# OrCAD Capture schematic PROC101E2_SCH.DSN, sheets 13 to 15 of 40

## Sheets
13 33. IO EXPANDER & TEST HEADER: size C; title: IO EXPANDER
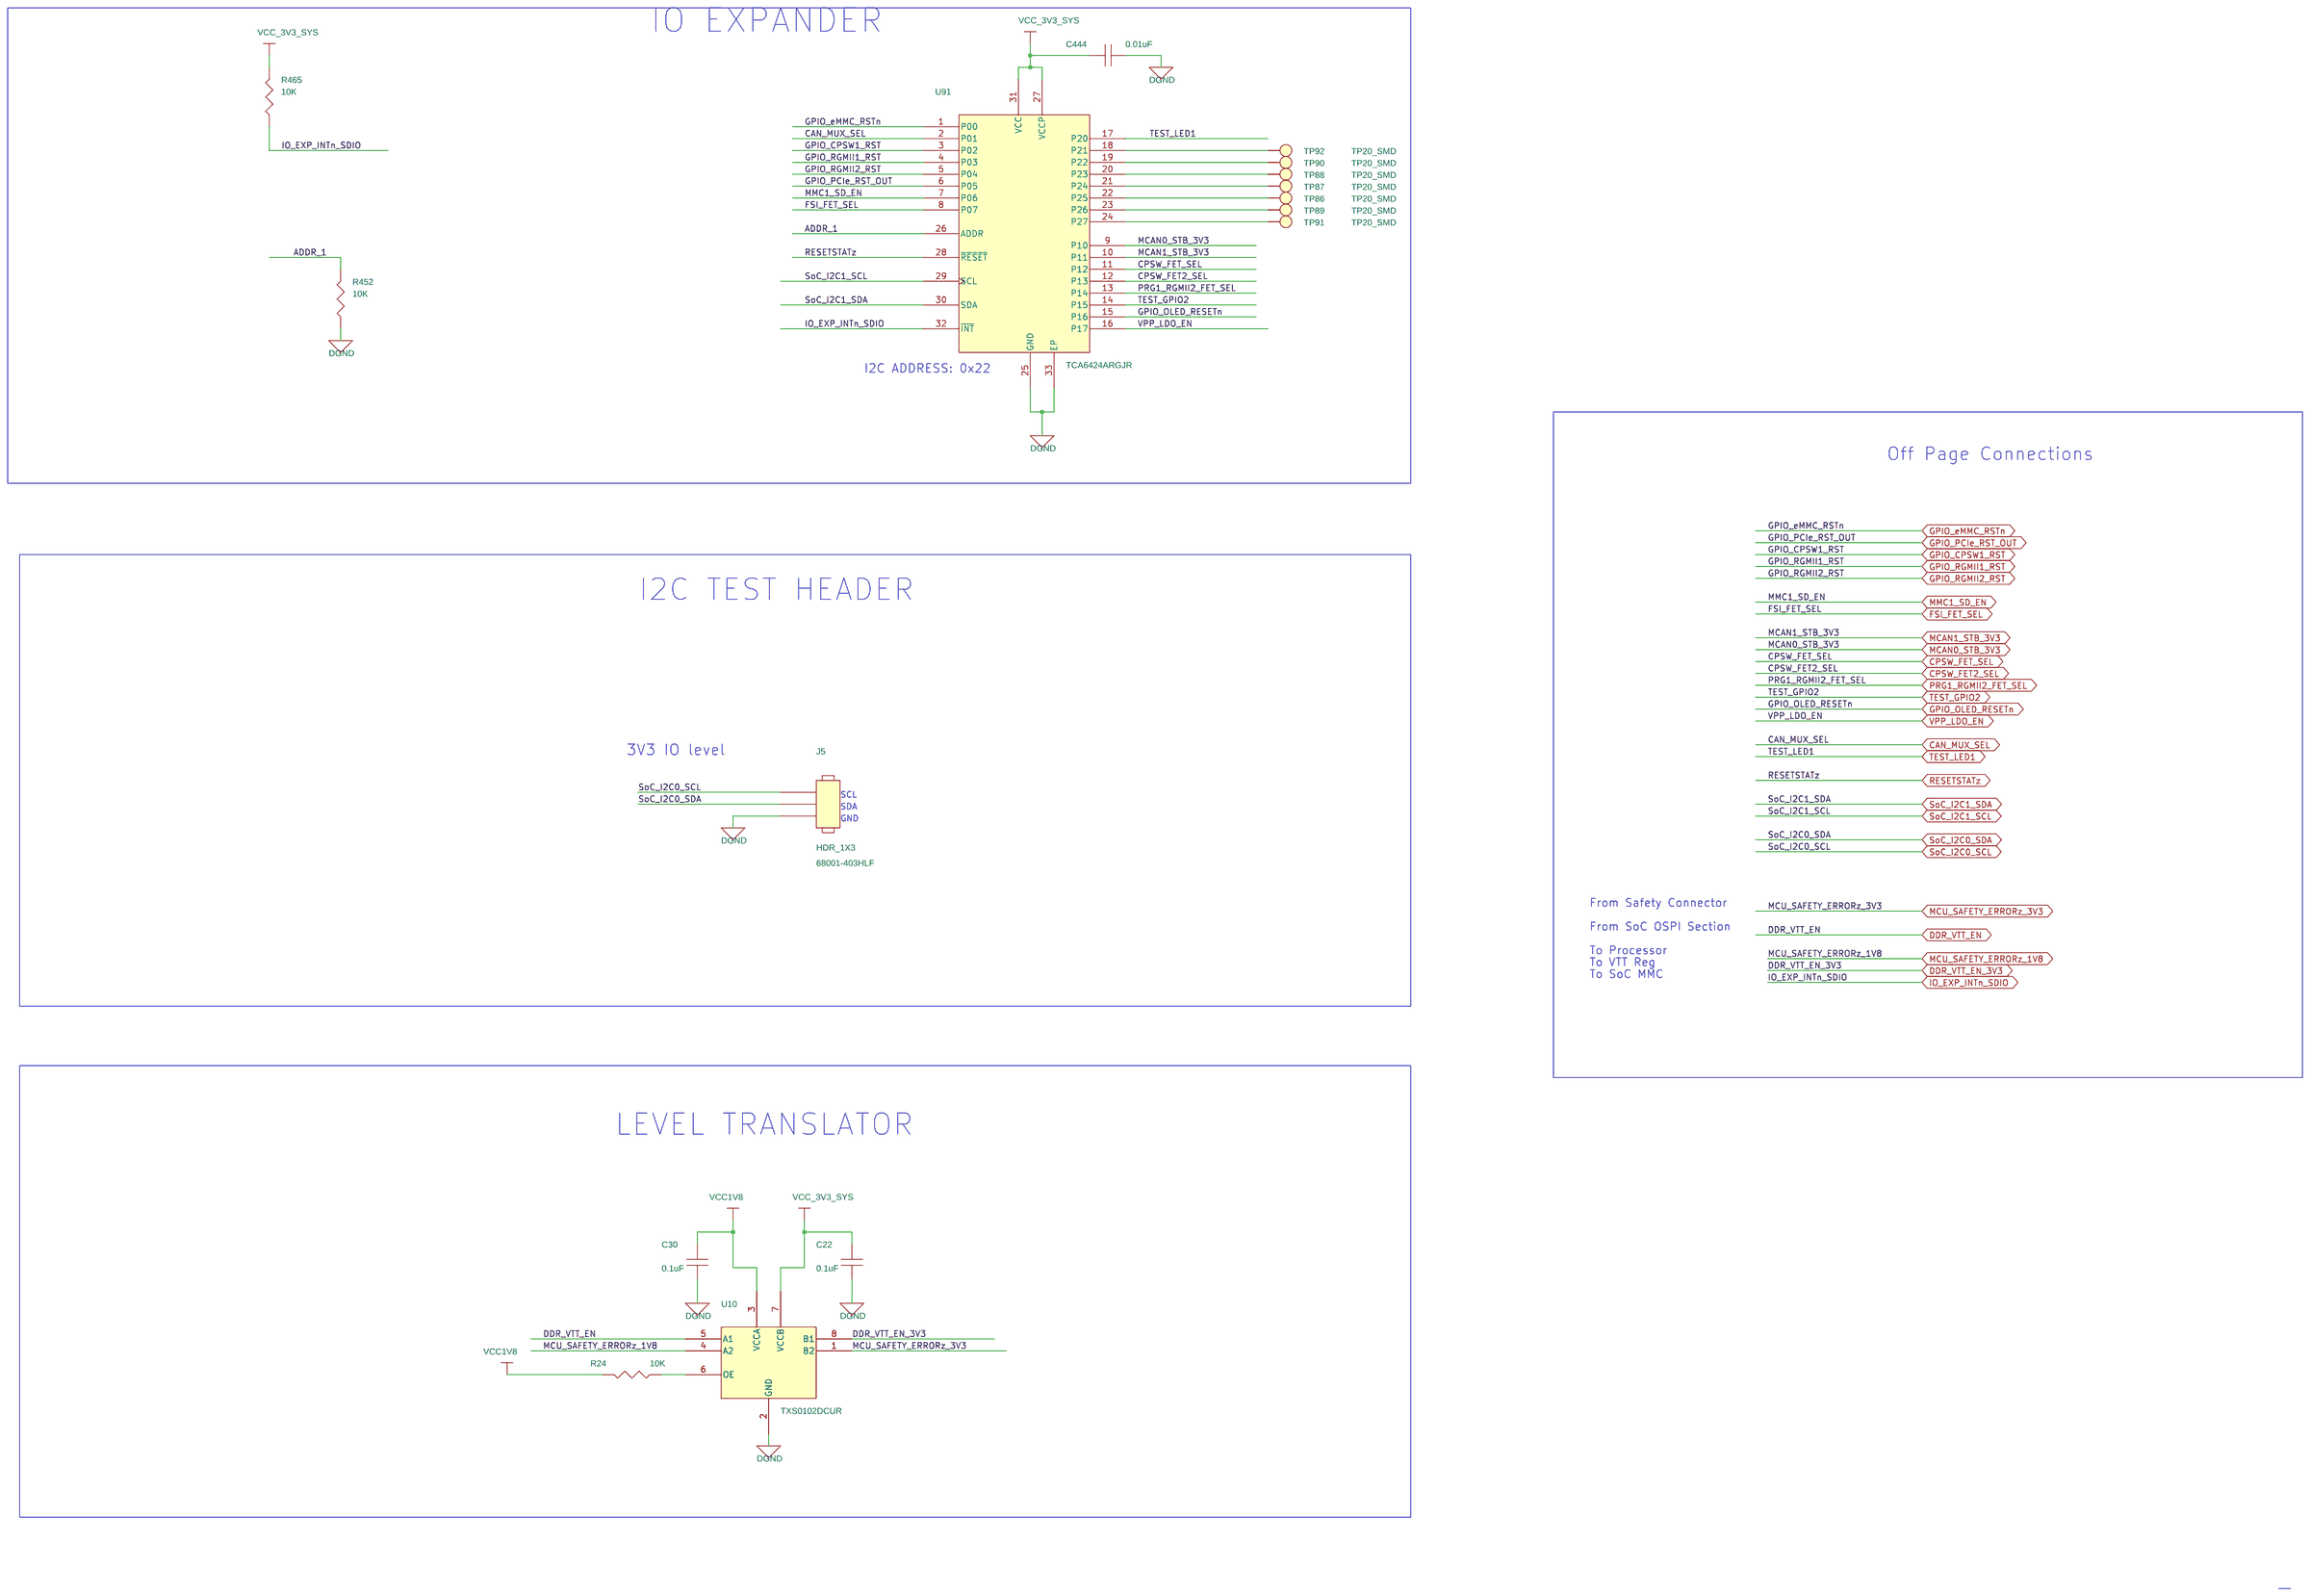
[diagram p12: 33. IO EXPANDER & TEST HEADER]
14 21. CURRENT MONITORING DEVICES: size C; title: CURRENT MONITORING DEVICES
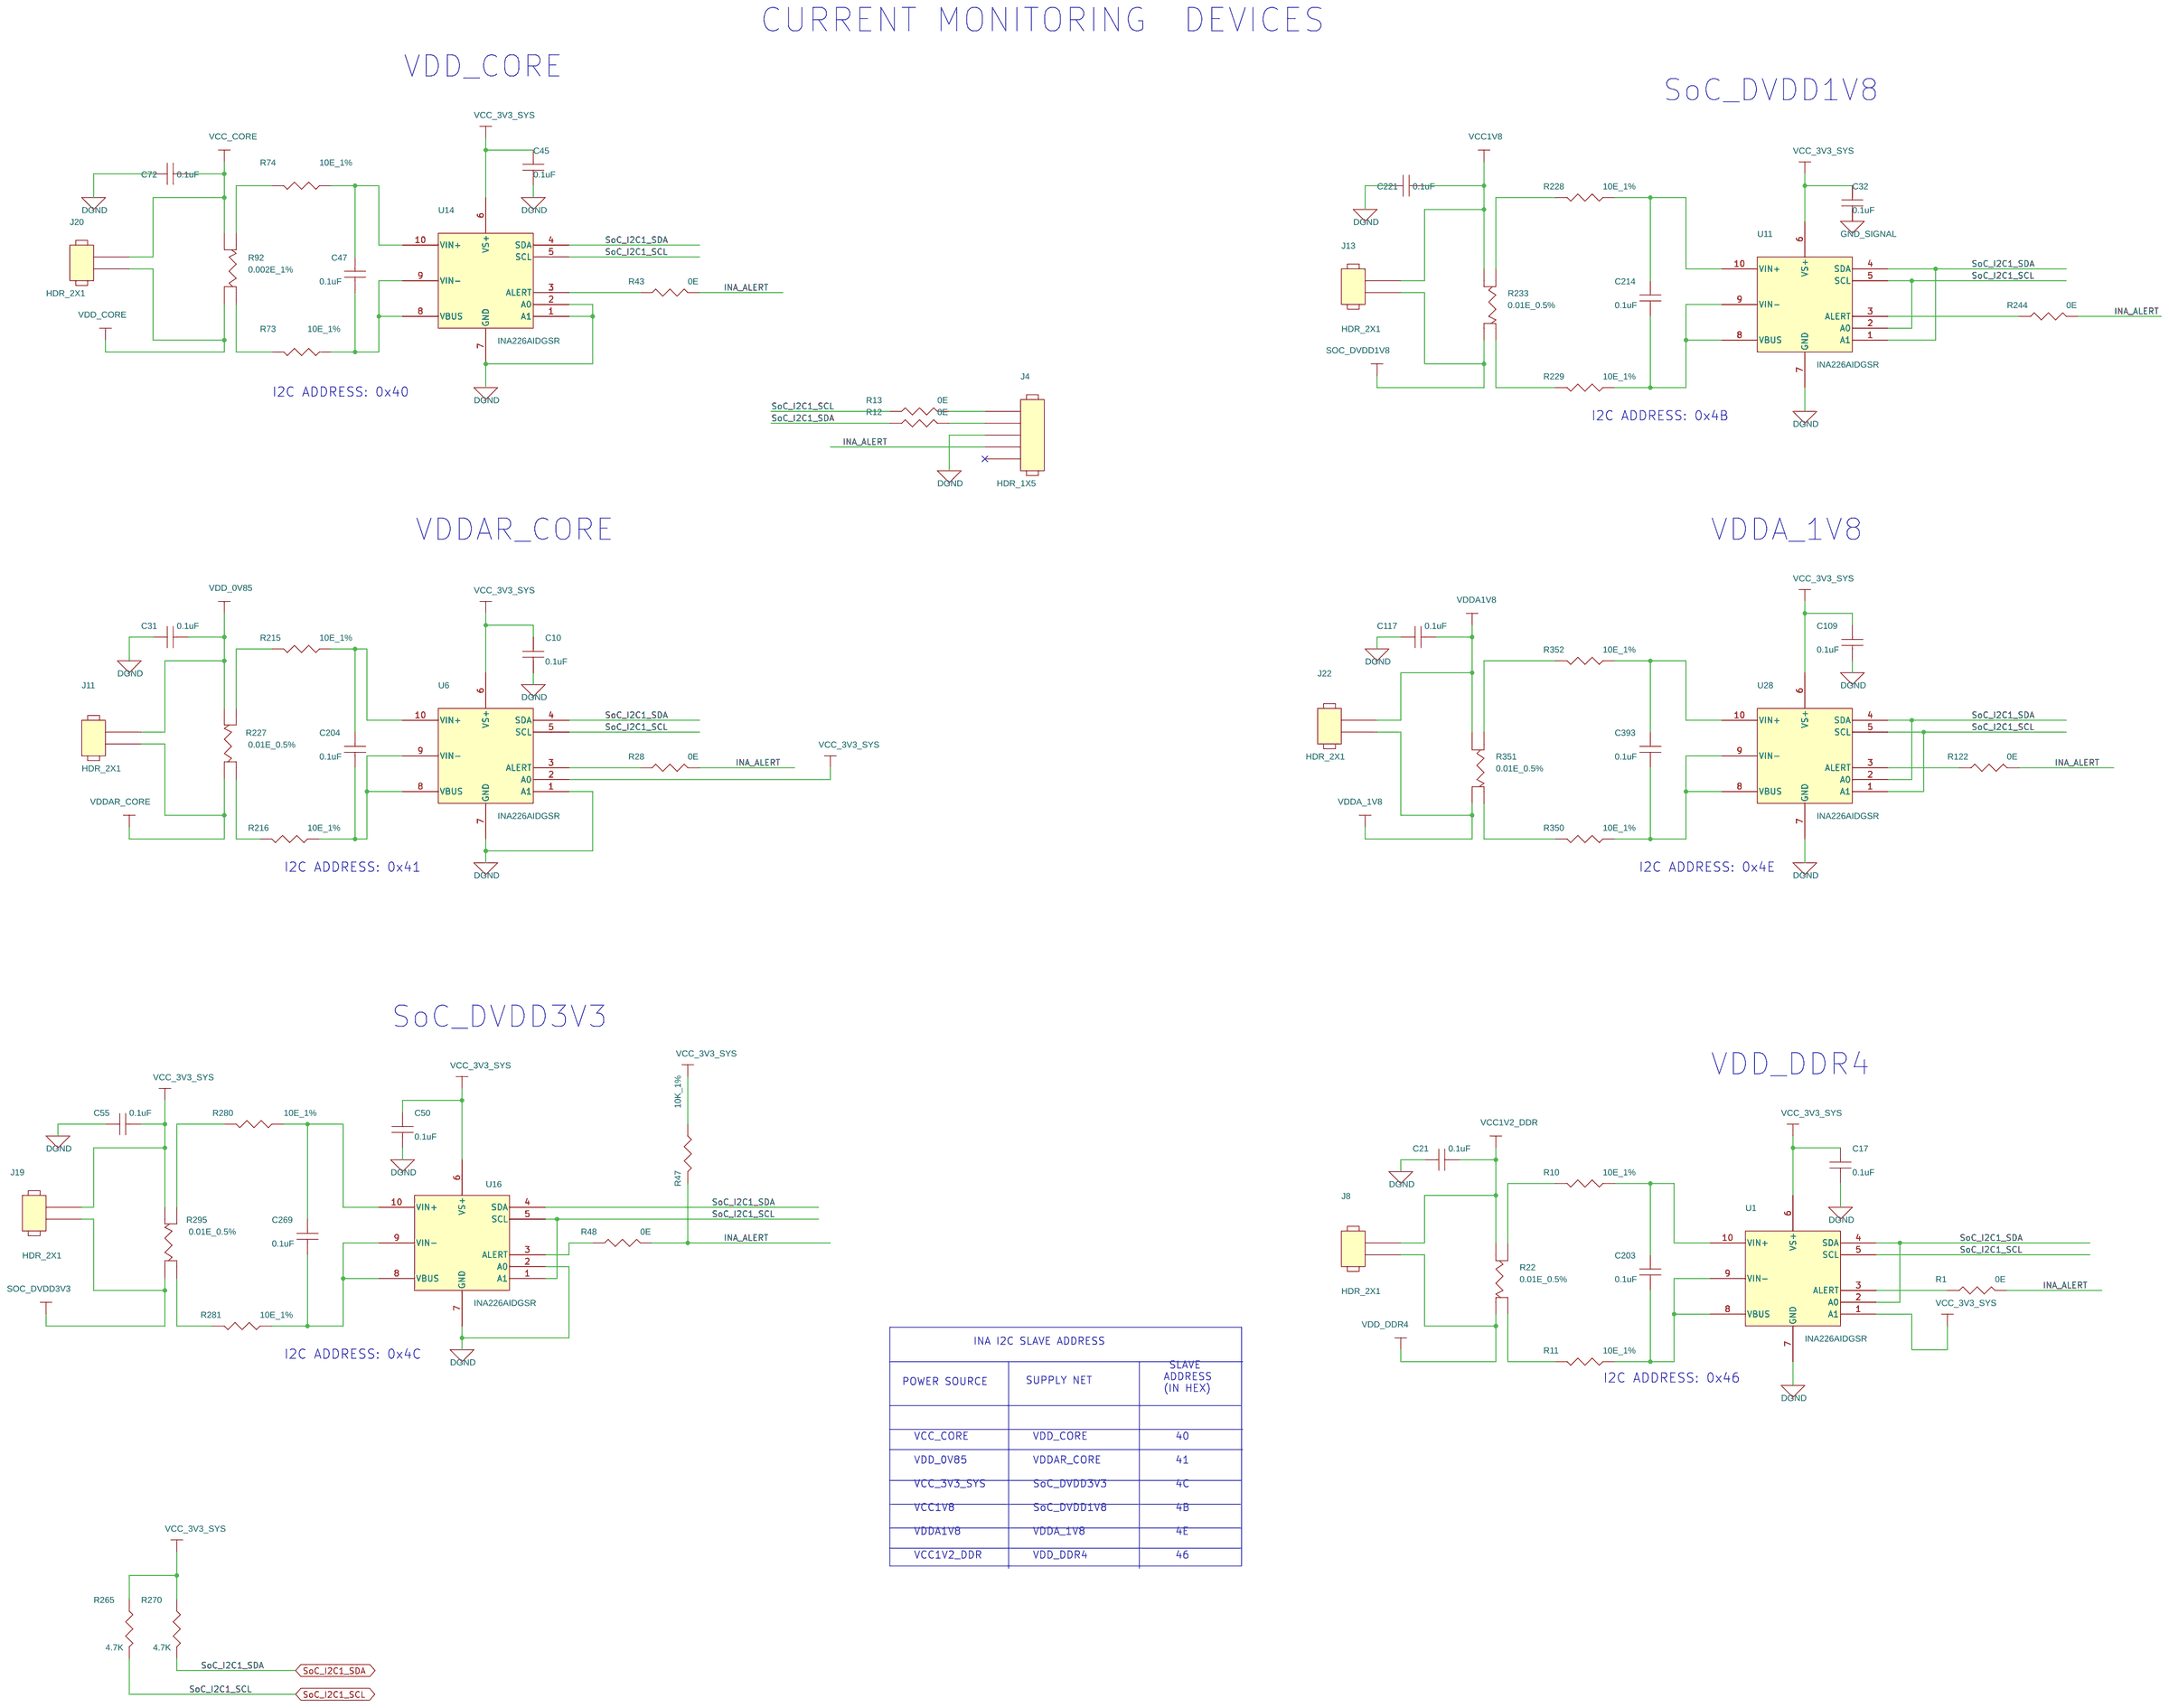
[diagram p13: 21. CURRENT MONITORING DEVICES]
15 38. SoC POWER SUPPLY: size C; title: SoC POWER SUPPLY
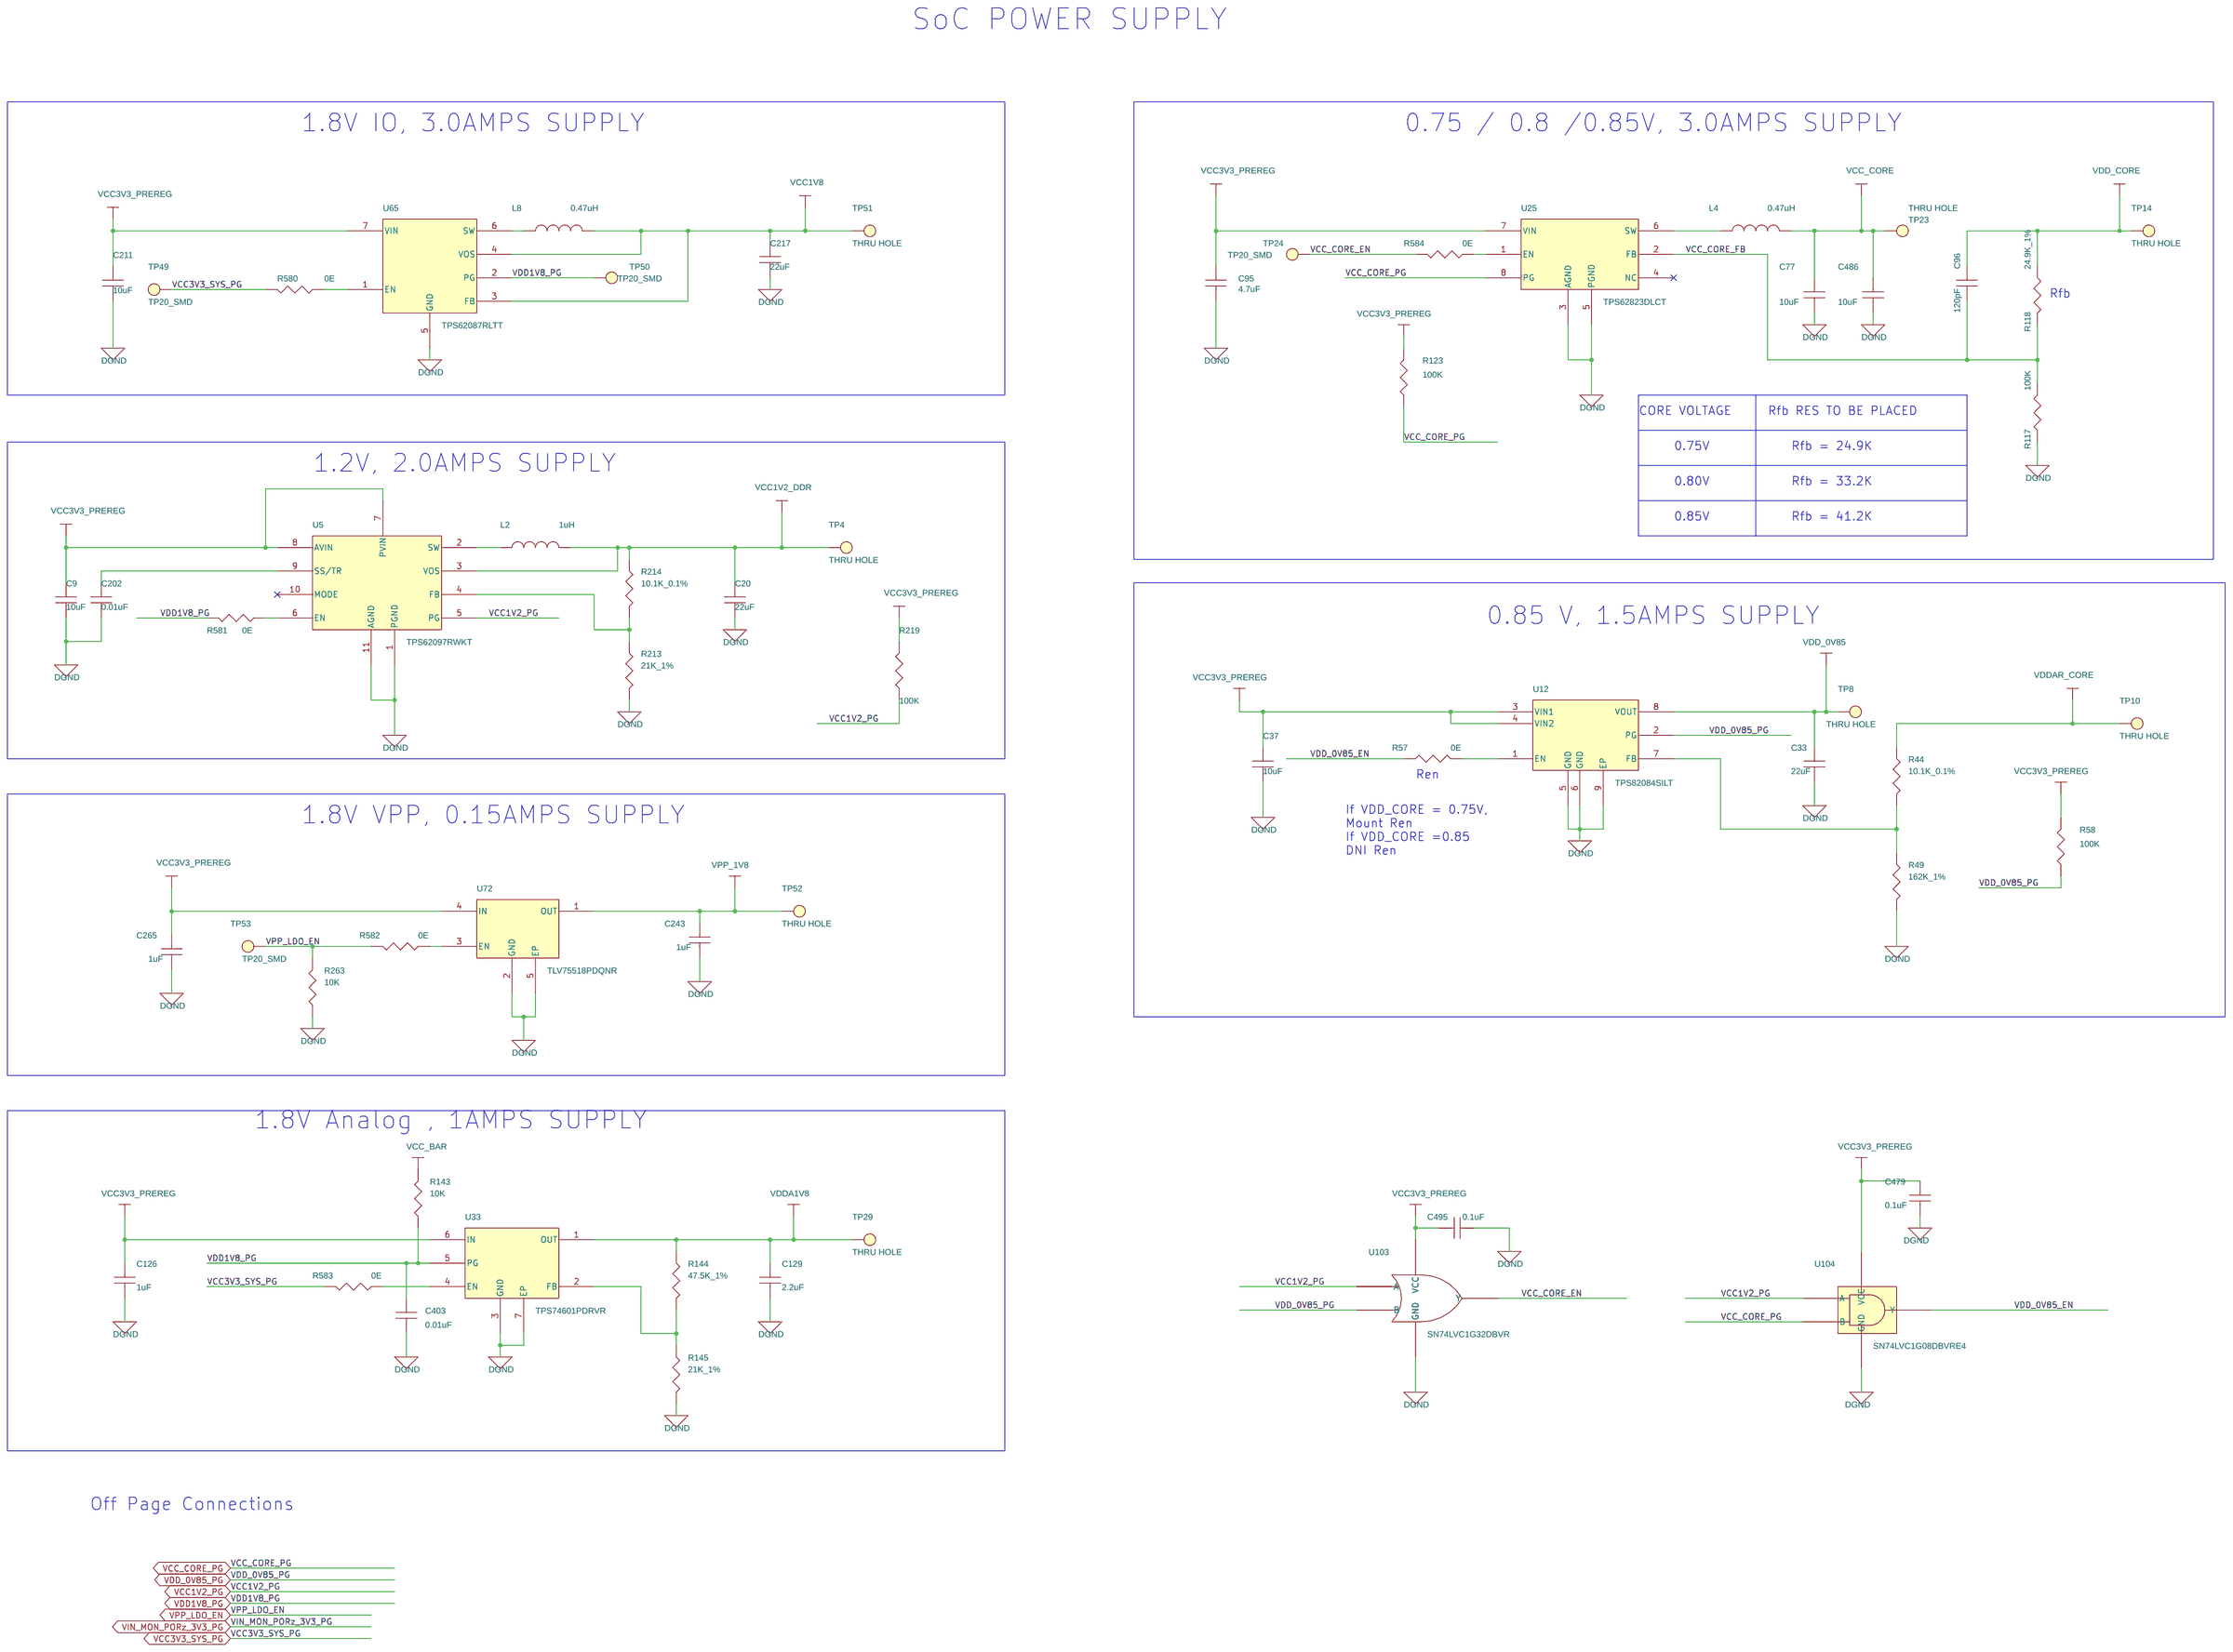
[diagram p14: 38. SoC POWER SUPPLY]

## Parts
sheet 21. CURRENT MONITORING DEVICES
C10  0.1uF  [CAP0402_0-75]
C17  0.1uF  [CAP0402_0-75]
C21  0.1uF  [CAP0402_0-75]
C31  0.1uF  [CAP0402_0-75]
C32  0.1uF  [CAP0402_0-75]
C45  0.1uF  [CAP0402_0-75]
C47  0.1uF  [CAP0402_0-75]
C50  0.1uF  [CAP0402_0-75]
C55  0.1uF  [CAP0402_0-75]
C72  0.1uF  [CAP0402_0-75]
C109  0.1uF  [CAP0402_0-75]
C117  0.1uF  [CAP0402_0-75]
C203  0.1uF  [CAP0402_0-75]
C204  0.1uF  [CAP0402_0-75]
C214  0.1uF  [CAP0402_0-75]
C221  0.1uF  [CAP0402_0-75]
C269  0.1uF  [CAP0402_0-75]
C393  0.1uF  [CAP0402_0-75]
J4  HDR_1X5  [HDR_5X1_100_S_T_11-2]
J8  HDR_2X1  [HDR_2X1_100_S_T_10-8]
J11  HDR_2X1  [HDR_2X1_100_S_T_10-8]
J13  HDR_2X1  [HDR_2X1_100_S_T_10-8]
J19  HDR_2X1  [HDR_2X1_100_S_T_10-8]
J20  HDR_2X1  [HDR_2X1_100_S_T_10-8]
J22  HDR_2X1  [HDR_2X1_100_S_T_10-8]
R1  0E  [RES0402_0-5]
R10  10E_1%  [RES0402_0-5]
R11  10E_1%  [RES0402_0-5]
R12  0E  [RES0402_0-5]
R13  0E  [RES0402_0-5]
R22  0.01E_0.5%  [RES1206-4TERM_0-75]
R28  0E  [RES0402_0-5]
R43  0E  [RES0402_0-5]
R47  10K_1%  [RES0402_0-5]
R48  0E  [RES0402_0-5]
R73  10E_1%  [RES0402_0-5]
R74  10E_1%  [RES0402_0-5]
R92  0.002E_1%  [RES2512-4TERM_0-75]
R122  0E  [RES0402_0-5]
R215  10E_1%  [RES0402_0-5]
R216  10E_1%  [RES0402_0-5]
R227  0.01E_0.5%  [RES1206-4TERM_0-75]
R228  10E_1%  [RES0402_0-5]
R229  10E_1%  [RES0402_0-5]
R233  0.01E_0.5%  [RES1206-4TERM_0-75]
R244  0E  [RES0402_0-5]
R265  4.7K  [RES0402_0-5]
R270  4.7K  [RES0402_0-5]
R280  10E_1%  [RES0402_0-5]
R281  10E_1%  [RES0402_0-5]
R295  0.01E_0.5%  [RES1206-4TERM_0-75]
R350  10E_1%  [RES0402_0-5]
R351  0.01E_0.5%  [RES1206-4TERM_0-75]
R352  10E_1%  [RES0402_0-5]
U1  INA226AIDGSR  [MSOP10_19-68_120X120_1-1]
U6  INA226AIDGSR  [MSOP10_19-68_120X120_1-1]
U11  INA226AIDGSR  [MSOP10_19-68_120X120_1-1]
U14  INA226AIDGSR  [MSOP10_19-68_120X120_1-1]
U16  INA226AIDGSR  [MSOP10_19-68_120X120_1-1]
U28  INA226AIDGSR  [MSOP10_19-68_120X120_1-1]
sheet 33. IO EXPANDER & TEST HEADER
C22  0.1uF  [CAP0402_0-75]
C30  0.1uF  [CAP0402_0-75]
C444  0.01uF  [CAP0402_0-75]
J5  HDR_1X3  [HDR_3X1_100_S_T]
R24  10K  [RES0402_0-5]
R452  10K  [RES0402_0-5]
R465  10K  [RES0402_0-5]
TP86  TP20_SMD  [TP20_SMD]
TP87  TP20_SMD  [TP20_SMD]
TP88  TP20_SMD  [TP20_SMD]
TP89  TP20_SMD  [TP20_SMD]
TP90  TP20_SMD  [TP20_SMD]
TP91  TP20_SMD  [TP20_SMD]
TP92  TP20_SMD  [TP20_SMD]
U10  TXS0102DCUR  [VSSOP8_19-68_85X95_0-9]
U91  TCA6424ARGJR  [QFN32_19-68_200X200]
sheet 38. SoC POWER SUPPLY
C9  10uF  [CAP0402_0-75]
C20  22uF  [CAP0603_1]
C33  22uF  [CAP0603_1]
C37  10uF  [CAP0402_0-75]
C77  10uF  [CAP0402_0-75]
C95  4.7uF  [CAP0603_1]
C96  120pF  [CAP0402_0-75]
C126  1uF  [CAP0402_0-75]
C129  2.2uF  [CAP0402_0-75]
C202  0.01uF  [CAP0402_0-75]
C211  10uF  [CAP0603_1]
C217  22uF  [CAP0603_1]
C243  1uF  [CAP0402_0-75]
C265  1uF  [CAP0402_0-75]
C403  0.01uF  [CAP0402_0-75]
C479  0.1uF  [CAP0402_0-75]
C486  10uF  [CAP0402_0-75]
C495  0.1uF  [CAP0402_0-75]
L2  1uH  [IND_744316100_230X220_SMD_4-3]
L4  0.47uH  [IND_744373460047_270X270_SMD_3]
L8  0.47uH  [IND_744373460047_270X270_SMD_3]
R44  10.1K_0.1%  [RES0603_0-75]
R49  162K_1%  [RES0402_0-5]
R57  0E  [RES0402_0-5]
R58  100K  [RES0402_0-5]
R117  100K  [RES0402_0-5]
R118  24.9K_1%  [RES0402_0-5]
R123  100K  [RES0402_0-5]
R143  10K  [RES0402_0-5]
R144  47.5K_1%  [RES0402_0-5]
R145  21K_1%  [RES0402_0-5]
R213  21K_1%  [RES0402_0-5]
R214  10.1K_0.1%  [RES0603_0-75]
R219  100K  [RES0402_0-5]
R263  10K  [RES0402_0-5]
R580  0E  [RES0402_0-5]
R581  0E  [RES0402_0-5]
R582  0E  [RES0402_0-5]
R583  0E  [RES0402_0-5]
R584  0E  [RES0402_0-5]
TP4  THRU HOLE  [TP_40X65]
TP8  THRU HOLE  [TP_40X65]
TP10  THRU HOLE  [TP_40X65]
TP14  THRU HOLE  [TP_40X65]
TP23  THRU HOLE  [TP_40X65]
TP24  TP20_SMD  [TP20_SMD]
TP29  THRU HOLE  [TP_40X65]
TP49  TP20_SMD  [TP20_SMD]
TP50  TP20_SMD  [TP20_SMD]
TP51  THRU HOLE  [TP_40X65]
TP52  THRU HOLE  [TP_40X65]
TP53  TP20_SMD  [TP20_SMD]
U5  TPS62097RWKT  [VQFNHR11_TPS62097_80X80_1]
U12  TPS82084SILT  [uSIP8_TPS82084_110X120_1-4]
U25  TPS62823DLCT  [VSONHR8_TPS62823_60X80_1]
U33  TPS74601PDRVR  [SON6_25-59_85X85_0-8]
U65  TPS62087RLTT  [VSONHR7_TPS62085_80X80_1]
U72  TLV75518PDQNR  [X2SON4_TLV71318P_40X40_0-4]
U103  SN74LVC1G32DBVR  [SOT23-5_1-5]
U104  SN74LVC1G08DBVRE4  [SOT23-5]

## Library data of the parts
C10 C17 C21 C22 C30-C32 C45 C47 C50 C55 C72 C109 C117 C203 C204 C214 C221 C269 C393 C479 C495 = CAP: CAP CERAMIC 0.1uF 25V 20% X5R 0402; Alt_Mfr_name: YAGEO AMERICA; Alt_Mfr_part_number: CC0402KRX5R8BB104; Chkd/date: MANIRAJA/170820; Crtd /date: ALVY/170820; Custom_Duty: 15%; Customs_HS_Code: 85322990; Distributor_name: DIGIKEY; Distributor_part_number: 732-7495-1-ND; Footprint Path: Y:\MIS_DATABASE\Library\ALTIUM_TOOL\PCB_FOOTPRINTS\Altium_Footprint_Lib.PcbLib; Height: 0.55MM; Library Path: Y:\MIS_DATABASE\Library\ALTIUM_TOOL\SCHEMATICS_PARTS\MS_DISCRETE_Library.schlib; Mfr_name: WURTH ELECTRONICS; Mfr_part_number: 885012105018; Mistral Part No: 120020080003-R; Package: 0402; Part_type: CAPACITORS\CERAMIC; Project: AM64x_EVM_BRD; RoHS: RoHS; Temperature: -55°C+85°C; Tolerance: 20%; Voltage: 25V; Wattage: NA; Weight: 0.65mg; Datasheet: Y:\MIS_DATABASE\DATASHEETS\CAPACITORS\885012105018.PDF
J4 = HEADER_5X1: CON HDR 1X5 2.54MM PITCH ST TH; Chkd/date: VASANTHA/310117; Crtd /date: MAZHAR/280405; Custom_Duty: 24%; Customs_HS_Code: 85369090; Distributor_name: DIGIKEY; Distributor_part_number: WM4003-ND; Footprint Path: Y:\MIS_DATABASE\Library\ALTIUM_TOOL\PCB_FOOTPRINTS\Altium_Footprint_Lib.PcbLib; Height: 11.17MM; Library Path: Y:\MIS_DATABASE\Library\ALTIUM_TOOL\SCHEMATICS_PARTS\MS_CONNECTOR_Library.schlib; Mfr_name: MOLEX; Mfr_part_number: 22-03-2051; Mistral Part No: 150009030262-R; Package: THRU-HOLE; Part_type: CONNECTOR\HEADERS; Project: HSWD; RoHS: RoHS; Temperature: NA; Tolerance: NA; Voltage: NA; Wattage: NA; Weight: 343mg; Datasheet: Y:\MIS_DATABASE\DATASHEETS\CONNECTORS\MOLEX022032021.PDF
J8 J11 J13 J19 J20 J22 = HEADER_2X1: CON HDR 2X1 2.54MM PITCH ST TH; Chkd/date: VASANTHA/060117; Crtd /date: MAZHAR/280405; Custom_Duty: 24%; Customs_HS_Code: 85369090; Distributor_name: DIGIKEY; Distributor_part_number: WM4000-ND; Footprint Path: Y:\MIS_DATABASE\Library\ALTIUM_TOOL\PCB_FOOTPRINTS\Altium_Footprint_Lib.PcbLib; Height: 10.79MM; Library Path: Y:\MIS_DATABASE\Library\ALTIUM_TOOL\SCHEMATICS_PARTS\MS_Connector_Library.schlib; Mfr_name: MOLEX; Mfr_part_number: 22-03-2021; Mistral Part No: 150009030246-R; Package: THRU-HOLE; Part_type: CONNECTOR\HEADERS; Project: FPGA EXTENDER CARD; RoHS: RoHS; Temperature: -0°C+75°C; Tolerance: NA; Voltage: NA; Wattage: NA; Weight: 139gm; Datasheet: Y:\MIS_DATABASE\DATASHEETS\CONNECTORS\HEADER_X4030.PDF
R1 R28 R43 R48 R122 R244 = RESISTOR: RES 0E 1/16W JUMPER 0402; Assembly: DNI; Chkd/date: VASANTHA/201216; Crtd /date: MUDDU/190810; Custom_Duty: 15%; Customs_HS_Code: 85332119; Distributor_name: DIGIKEY; Distributor_part_number: 541-0.0JCT-ND; Footprint Path: Y:\MIS_DATABASE\Library\ALTIUM_TOOL\PCB_FOOTPRINTS\Altium_Footprint_Lib.PcbLib; Height: 0.40MM; Library Path: Y:\MIS_DATABASE\Library\ALTIUM_TOOL\SCHEMATICS_PARTS\MS_DISCRETE_Library.schlib; Mfr_name: VISHAY; Mfr_part_number: CRCW04020000Z0ED; Mistral Part No: 110010080019-R; Package: 0402; Part_type: RESISTORS\FIXED; Project: PB_BUGBASE; RoHS: RoHS; Temperature: -55°C+155°C; Tolerance: NA; Voltage: NA; Wattage: 1/16W; Weight: 0.65mg; Datasheet: Y:\MIS_DATABASE\DATASHEETS\RESISTORS\CRCW0603.PDF
R10 R11 R73 R74 R215 R216 R228 R229 R280 R281 R350 R352 = RESISTOR: RES 10E 1/16W 1% 0402; Chkd/date: MANIRAJA/070218; Crtd /date: ALVY/070218; Custom_Duty: 15%; Customs_HS_Code: 85332119; Distributor_name: DIGIKEY; Distributor_part_number: 311-10.0LRCT-ND; Footprint Path: Y:\MIS_DATABASE\Library\ALTIUM_TOOL\PCB_FOOTPRINTS\Altium_Footprint_Lib.PcbLib; Height: 0.40MM; Library Path: Y:\MIS_DATABASE\Library\ALTIUM_TOOL\SCHEMATICS_PARTS\MS_DISCRETE_Library.schlib; Mfr_name: YAGEO AMERICA; Mfr_part_number: RC0402FR-0710RL; Mistral Part No: 110018020004-R; Package: 0402; Part_type: RESISTORS\FIXED; Project: TI_MAXIE_CPB; RoHS: RoHS; Temperature: -55°C+155°C; Tolerance: 1%; Voltage: NA; Wattage: 1/16W; Weight: 0.65mg; Datasheet: Y:\MIS_DATABASE\DATASHEETS\RESISTORS\RCXXXXL-SER_MAR18.PDF
R12 R13 R57 R580-R584 = RESISTOR: RES 0E 1/16W JUMPER 0402; Chkd/date: VASANTHA/201216; Crtd /date: MUDDU/190810; Custom_Duty: 15%; Customs_HS_Code: 85332119; Distributor_name: DIGIKEY; Distributor_part_number: 541-0.0JCT-ND; Footprint Path: Y:\MIS_DATABASE\Library\ALTIUM_TOOL\PCB_FOOTPRINTS\Altium_Footprint_Lib.PcbLib; Height: 0.40MM; Library Path: Y:\MIS_DATABASE\Library\ALTIUM_TOOL\SCHEMATICS_PARTS\MS_DISCRETE_Library.schlib; Mfr_name: VISHAY; Mfr_part_number: CRCW04020000Z0ED; Mistral Part No: 110010080019-R; Package: 0402; Part_type: RESISTORS\FIXED; Project: PB_BUGBASE; RoHS: RoHS; Temperature: -55°C+155°C; Tolerance: NA; Voltage: NA; Wattage: 1/16W; Weight: 0.65mg; Datasheet: Y:\MIS_DATABASE\DATASHEETS\RESISTORS\CRCW0603.PDF
R22 R227 R233 R295 R351 = RESISTOR-4TERM: RES 0.01E 1/2W 0.5% 1206-4; Chkd/date: MANIRAJA/260917; Crtd /date: MANIRAJA/260917; Custom_Duty: 15%; Customs_HS_Code: 85332119; Distributor_name: DIGIKEY; Distributor_part_number: LVK12R010DERCT-ND; Footprint Path: Y:\MIS_DATABASE\Library\ALTIUM_TOOL\PCB_FOOTPRINTS\Altium_Footprint_Lib.PcbLib; Height: 0.65MM; Library Path: Y:\MIS_DATABASE\Library\ALTIUM_TOOL\SCHEMATICS_PARTS\MS_DISCRETE_Library.schlib; Mfr_name: OHMITE; Mfr_part_number: LVK12R010DER; Mistral Part No: 110017090009-R; Package: 1206-4; Part_type: RESISTORS\FIXED; Project: TI_MAXIE_CPB; RoHS: RoHS; Temperature: -40°C+125°C; Tolerance: 0.5%; Voltage: NA; Wattage: 1/2W; Weight: 16.2mg; Datasheet: Y:\MIS_DATABASE\DATASHEETS\RESISTORS\LVK-SERIES.PDF
R47 = RESISTOR: RES 10K 1/16W 1% 0402; Chkd/date: VASANTHA/201216; Crtd /date: GEETHA/290506; Custom_Duty: 15%; Customs_HS_Code: 85332119; Distributor_name: DIGIKEY; Distributor_part_number: 311-10.0KLRTR-ND; Footprint Path: Y:\MIS_DATABASE\Library\ALTIUM_TOOL\PCB_FOOTPRINTS\Altium_Footprint_Lib.PcbLib; Height: 0.40MM; Library Path: Y:\MIS_DATABASE\Library\ALTIUM_TOOL\SCHEMATICS_PARTS\MS_DISCRETE_Library.schlib; Mfr_name: YAGEO AMERICA; Mfr_part_number: RC0402FR-0710KL; Mistral Part No: 110015090015-R; Package: 0402; Part_type: RESISTORS\FIXED; Project: VOCERA; RoHS: RoHS; Temperature: -55°C+155°C; Tolerance: 1%; Voltage: NA; Wattage: 1/16W; Weight: 0.65mg; Datasheet: Y:\MIS_DATABASE\DATASHEETS\RESISTORS\RCXXXXL-SER_MAR18.PDF
R92 = RESISTOR-4TERM: RES 0.002E 2W 1% 2512-4; Chkd/date: MANIRAJA/260917; Crtd /date: MANIRAJA/260917; Custom_Duty: 15%; Customs_HS_Code: 85332119; Distributor_name: DIGIKEY; Distributor_part_number: LVK25R002FERCT-ND; Footprint Path: Y:\MIS_DATABASE\Library\ALTIUM_TOOL\PCB_FOOTPRINTS\Altium_Footprint_Lib.PcbLib; Height: 0.70MM; Library Path: Y:\MIS_DATABASE\Library\ALTIUM_TOOL\SCHEMATICS_PARTS\MS_DISCRETE_Library.schlib; Mfr_name: OHMITE; Mfr_part_number: LVK25R002FER; Mistral Part No: 110017090010-R; Package: 2512-4; Part_type: RESISTORS\FIXED; Project: TI_MAXIE_CPB; RoHS: RoHS; Temperature: -40°C+125°C; Tolerance: 1%; Voltage: NA; Wattage: 2W; Weight: NA; Datasheet: Y:\MIS_DATABASE\DATASHEETS\RESISTORS\LVK-SERIES.PDF
R265 R270 = RESISTOR: RES 4.7K 1/16W 5% 0402; Chkd/date: VASANTHA/130516; Crtd /date: VASANTHA/130516; Custom_Duty: 15%; Customs_HS_Code: 85332119; Distributor_name: DIGIKEY; Distributor_part_number: 311-4.7KJRCT-ND; Footprint Path: Y:\MIS_DATABASE\Library\ALTIUM_TOOL\PCB_FOOTPRINTS\Altium_Footprint_Lib.PcbLib; Height: 0.40MM; Library Path: Y:\MIS_DATABASE\Library\ALTIUM_TOOL\SCHEMATICS_PARTS\MS_DISCRETE_Library.schlib; Mfr_name: YAGEO AMERICA; Mfr_part_number: RC0402JR-074K7L; Mistral Part No: 110011060001-R; Package: 0402; Part_type: RESISTORS\FIXED; Project: TMDXCSK368; RoHS: RoHS; Temperature: -55°C+155°C; Tolerance: 5%; Voltage: NA; Wattage: 1/16W; Weight: 0.65mg; Datasheet: Y:\MIS_DATABASE\DATASHEETS\RESISTORS\RCXXXXL-SER_MAR18.PDF
U1 U6 U11 U14 U16 U28 = INA226AIDGS_MSOP10: IC BI-DIRECTIONAL CURRENT MONITER MSOP10; Chkd/date: MANIRAJA/050417; Crtd /date: MANIRAJA/050417; Custom_Duty: 15%; Customs_HS_Code: 85423100; Distributor_name: DIGIKEY; Distributor_part_number: 296-29034-1-ND; Footprint Path: Y:\MIS_DATABASE\Library\ALTIUM_TOOL\PCB_FOOTPRINTS\Altium_Footprint_Lib.PcbLib; Height: 1.10MM; Library Path: Y:\MIS_DATABASE\Library\ALTIUM_TOOL\SCHEMATICS_PARTS\MS_MISCINTERFACE_Library.schlib; Mfr_name: TEXAS INSTRUMENTS; Mistral Part No: 141011080019-R; Package: MSOP10; Part_type: ICS\INTERFACE; Project: DM385EVM_BASE-BOARD; RoHS: RoHS; Temperature: -40°C+125°C; Tolerance: NA; Voltage: NA; Wattage: NA; Weight: NA; Datasheet: Y:\MIS_DATABASE\DATASHEETS\ICS\INTERFACE\INA226.PDF
C202 C403 C444 = CAP: CAP CERAMIC 0.01uF 25V 10% X7R 0402; Chkd/date: MANIRAJA/170820; Crtd /date: ALVY/170820; Custom_Duty: 15%; Customs_HS_Code: 85322990; Distributor_name: DIGIKEY; Distributor_part_number: 732-7545-1-ND; Footprint Path: Y:\MIS_DATABASE\Library\ALTIUM_TOOL\PCB_FOOTPRINTS\Altium_Footprint_Lib.PcbLib; Height: 0.55MM; Library Path: Y:\MIS_DATABASE\Library\ALTIUM_TOOL\SCHEMATICS_PARTS\MS_DISCRETE_Library.schlib; Mfr_name: WURTH ELECTRONICS; Mfr_part_number: 885012205050; Mistral Part No: 120011090040-R; Package: 0402; Part_type: CAPACITORS\CERAMIC; Project: AM64x_EVM_BRD; RoHS: RoHS; Temperature: -55°C+125°C; Tolerance: 10%; Voltage: 25V; Wattage: NA; Weight: 0.65mg; Datasheet: Y:\MIS_DATABASE\DATASHEETS\CAPACITORS\885012205050.PDF
J5 = HEADER_3X1: HDR 1X3 2.54MM PITCH ST TH; Chkd/date: VASANTHA/290616; Crtd /date: VASANTHA/290616; Custom_Duty: 15%; Customs_HS_Code: 85322990; Distributor_name: DIGIKEY; Distributor_part_number: 609-3471-ND; Height: 8.58MM; Mfr_name: FCI; Mfr_part_number: 68001-403HLF; Mistral Part No: 150016060025-R; Package: THRU-HOLE; Part_type: CONNECTOR\HEADERS; Project: IKEYP; RoHS: RoHS; Temperature: -40°C+105°C; Tolerance: NA; Voltage: NA; Wattage: NA; Weight: NA; Datasheet: Y:\MIS_DATABASE\DATASHEETS\CONNECTORS\68000.PDF
R24 R143 R263 R452 R465 = RESISTOR: RES 10K 1/16W 5% 0402; Chkd/date: VASANTHA/061216; Crtd /date: MAZHAR/230805; Custom_Duty: 15%; Customs_HS_Code: 85332119; Distributor_name: DIGIKEY; Distributor_part_number: 311-10KJRCT-ND; Footprint Path: Y:\MIS_DATABASE\Library\ALTIUM_TOOL\PCB_FOOTPRINTS\Altium_Footprint_Lib.PcbLib; Height: 0.40MM; Library Path: Y:\MIS_DATABASE\Library\ALTIUM_TOOL\SCHEMATICS_PARTS\MS_DISCRETE_Library.schlib; Mfr_name: YAGEO AMERICA; Mfr_part_number: RC0402JR-0710KL; Mistral Part No: 110011060021-R; Package: 0402; Part_type: RESISTORS\FIXED; Project: HSE; RoHS: RoHS; Temperature: -55°C+155°C; Tolerance: 5%; Voltage: NA; Wattage: 1/16W; Weight: 0.65mg; Datasheet: Y:\MIS_DATABASE\DATASHEETS\RESISTORS\RCXXXXL-SER_MAR18.PDF
TP24 TP49 TP50 TP53 TP86-TP92 = TESTPOINT: TESTPOINT CIR 20 SMD; Chkd/date: SHREESHAIL/171006; Crtd /date: MAZHAR/171006; Custom_Duty: NA; Customs_HS_Code: NA; Distributor_name: NA; Distributor_part_number: NA; Footprint Path: Y:\MIS_DATABASE\Library\ALTIUM_TOOL\PCB_FOOTPRINTS\Altium_Footprint_Lib.PcbLib; Height: NA; Library Path: Y:\MIS_DATABASE\Library\ALTIUM_TOOL\SCHEMATICS_PARTS\MS_DISCRETE_Library.schlib; MECHANICAL 3D STEP FILE: NA; Mfr_name: LOCAL; Mistral Part No: NA; Package: SMD; Project: BT MODULE_CSRBC04; RoHS: NA; Temperature: NA; Tolerance: NA; Voltage: NA; Wattage: NA; Weight: NA; Datasheet: NA
U10 = TXS0102DCUR_VSSOP8: IC 2BIT BI-DIR VOLTAGE-LEVEL TRANSLATOR US8(VSSOP8); Chkd/date: MANIRAJA/130617; Crtd /date: SHREESHAIL/190108; Custom_Duty: 15%; Customs_HS_Code: 85423100; Distributor_name: DIGIKEY; Distributor_part_number: 296-21931-1-ND; Footprint Path: Y:\MIS_DATABASE\Library\ALTIUM_TOOL\PCB_FOOTPRINTS\Altium_Footprint_Lib.PcbLib; Height: 0.90MM; Library Path: Y:\MIS_DATABASE\Library\ALTIUM_TOOL\SCHEMATICS_PARTS\MS_MISCINTERFACE_Library.schlib; Mfr_name: TEXAS INSTRUMENTS; Mistral Part No: 141009030376-R; Package: US8; Part_type: ICS\INTERFACE\LEVEL TRANSLATOR; Project: SD_WATERLOO; RoHS: RoHS; Temperature: -40°C+85°C; Tolerance: NA; Voltage: NA; Wattage: NA; Weight: 9.6mg; Datasheet: Y:\MIS_DATABASE\DATASHEETS\ICS\INTERFACE\TXS0102.PDF
U91 = TCA6424ARGJR_QFN32: IC I2C I/O EXPANDER 24B UQFN32; Chkd/date: NAVEED/100715; Crtd /date: NAVEED/100914; Custom_Duty: 15%; Customs_HS_Code: 85423100; Distributor_name: DIGIKEY; Distributor_part_number: 296-27844-1-ND; Height: 0.60MM; Mfr_name: TEXAS INSTRUMENTS; Mistral Part No: 141014090009-R; Package: UQFN32; Part_type: ICS\DIGITAL\BUSTRANSCEIVER; Project: ZK_BIOMETRIC; RoHS: RoHS; Temperature: -40°C+85°C; Weight: NA; Datasheet: Y:\MIS_DATABASE\DATASHEETS\ICS\DIGITAL\BUSTRANSCEIVER\TCA6424AR.PDF
C9 C37 C77 C486 = CAP: CAP CERAMIC 10uF 10V 20% X5R 0402; Chkd/date: MANIRAJA/300520; Crtd /date: ALVY/260520; Custom_Duty: 15%; Customs_HS_Code: 85322990; Distributor_name: DIGIKEY; Distributor_part_number: 490-GRM155R61A106ME11DTR-ND; Footprint Path: Y:\MIS_DATABASE\Library\ALTIUM_TOOL\PCB_FOOTPRINTS\Altium_Footprint_Lib.PcbLib; Height: 0.55MM; Library Path: Y:\MIS_DATABASE\Library\ALTIUM_TOOL\SCHEMATICS_PARTS\MS_DISCRETE_Library.schlib; Mfr_name: MURATA; Mfr_part_number: GRM155R61A106ME11D; Mistral Part No: 120013110019-R; Package: 0402; Part_type: CAPACITORS\CERAMIC; Project: QCS610_NANOSOM; RoHS: RoHS; Temperature: -55°C+85°C; Tolerance: 20%; Voltage: 10V; Wattage: NA; Weight: 3.1mg; Datasheet: Y:\MIS_DATABASE\DATASHEETS\CAPACITORS\MURATA-GXX-SER_NOV17.PDF
C20 C33 C217 = CAP: CAP CERAMIC 22uF 6.3V 20% X5R 0603; Chkd/date: JEBRAN/090915; Crtd /date: JEBRAN/090915; Custom_Duty: 15%; Customs_HS_Code: 85322990; Distributor_name: DIGIKEY; Distributor_part_number: 490-7611-2-ND; Footprint Path: Y:\MIS_DATABASE\Library\ALTIUM_TOOL\PCB_FOOTPRINTS\Altium_Footprint_Lib.PcbLib; Height: 1.00MM; Library Path: Y:\MIS_DATABASE\Library\ALTIUM_TOOL\SCHEMATICS_PARTS\MS_DISCRETE_Library.schlib; Mfr_name: MURATA; Mfr_part_number: GRM188R60J226MEA0; Mistral Part No: 120015090007-R; Package: 0603; Part_type: CAPACITORS\CERAMIC; Project: OCTBTS_3000; RoHS: RoHS; Temperature: -55°C+85°C; Tolerance: 20%; Voltage: 6.3V; Wattage: NA; Weight: 6.3mg; Datasheet: Y:\MIS_DATABASE\DATASHEETS\CAPACITORS\MURATA-GXX-SER_NOV17.PDF
C95 = CAP: CAP CERAMIC 4.7uF 16V 10% X5R 0603; Chkd/date: MANIRAJA/131217; Crtd /date: ALVY/131217; Custom_Duty: 15%; Customs_HS_Code: 85322990; Distributor_name: DIGIKEY; Distributor_part_number: 311-1785-1-ND; Footprint Path: Y:\MIS_DATABASE\Library\ALTIUM_TOOL\PCB_FOOTPRINTS\Altium_Footprint_Lib.PcbLib; Height: 0.95MM; Library Path: Y:\MIS_DATABASE\Library\ALTIUM_TOOL\SCHEMATICS_PARTS\MS_DISCRETE_Library.schlib; Mfr_name: YAGEO AMERICA; Mfr_part_number: CC0603KRX5R7BB475; Mistral Part No: 120011050004-R; Package: 0603; Part_type: CAPACITORS\CERAMIC; Project: ASL_LIU_TYPE-II; RoHS: RoHS; Temperature: -55°C+85°C; Tolerance: 10%; Voltage: 16V; Wattage: NA; Weight: 2mg; Datasheet: Y:\MIS_DATABASE\DATASHEETS\CAPACITORS\YACC-X5R.PDF
C96 = CAP: CAP CERAMIC 120pF 50V 5% C0G(NP0) 0402; Chkd/date: MANIRAJA/080520; Crtd /date: ALVY/070520; Custom_Duty: 15%; Customs_HS_Code: 85322990; Distributor_name: DIGIKEY; Distributor_part_number: 311-3337-1-ND; Footprint Path: Y:\MIS_DATABASE\Library\ALTIUM_TOOL\PCB_FOOTPRINTS\Altium_Footprint_Lib.PcbLib; Height: 0.55MM; Library Path: Y:\MIS_DATABASE\Library\ALTIUM_TOOL\SCHEMATICS_PARTS\MS_DISCRETE_Library.schlib; Mfr_name: YAGEO AMERICA; Mfr_part_number: CC0402JRNPO9BN121; Mistral Part No: 120014040005-R; Package: 0402; Part_type: CAPACITORS\CERAMIC; Project: AM64x-GP_EVM BRD; RoHS: RoHS; Temperature: -55°C+125°C; Tolerance: 5%; Voltage: 50V; Wattage: NA; Weight: 12mg; Datasheet: Y:\MIS_DATABASE\DATASHEETS\CAPACITORS\YACC-NPO.PDF
C126 C243 C265 = CAP: CAP CERAMIC 1uF 10V 20% X5R 0402; Chkd/date: MANIRAJA/210820; Crtd /date: ALVY/190820; Custom_Duty: 15%; Customs_HS_Code: 85322990; Distributor_name: DIGIKEY; Distributor_part_number: 732-7489-1-ND; Footprint Path: Y:\MIS_DATABASE\Library\ALTIUM_TOOL\PCB_FOOTPRINTS\Altium_Footprint_Lib.PcbLib; Height: 0.55MM; Library Path: Y:\MIS_DATABASE\Library\ALTIUM_TOOL\SCHEMATICS_PARTS\MS_DISCRETE_Library.schlib; Mfr_name: WURTH ELECTRONICS; Mfr_part_number: 885012105012; Mistral Part No: 120020080009-R; Package: 0402; Part_type: CAPACITORS\CERAMIC; Project: AM64x_EVM_BRD; RoHS: RoHS; Temperature: -55°C+85°C; Tolerance: 20%; Voltage: 10V; Wattage: NA; Weight: 0.65mg; Datasheet: Y:\MIS_DATABASE\DATASHEETS\CAPACITORS\885012105012.PDF
C129 = CAP: CAP CERAMIC 2.2uF 10V 20% X5R 0402; Chkd/date: MANIRAJA/170820; Crtd /date: ALVY/170820; Custom_Duty: 15%; Customs_HS_Code: 85322990; Distributor_name: DIGIKEY; Distributor_part_number: 732-7490-1-ND; Footprint Path: Y:\MIS_DATABASE\Library\ALTIUM_TOOL\PCB_FOOTPRINTS\Altium_Footprint_Lib.PcbLib; Height: 0.55MM; Library Path: Y:\MIS_DATABASE\Library\ALTIUM_TOOL\SCHEMATICS_PARTS\MS_DISCRETE_Library.schlib; Mfr_name: WURTH ELECTRONICS; Mfr_part_number: 885012105013; Mistral Part No: 120019040036-R; Package: 0402; Part_type: CAPACITORS\CERAMIC; Project: AM64x_EVM_BRD; RoHS: RoHS; Temperature: -55°C+85°C; Tolerance: 20%; Voltage: 10V; Wattage: NA; Weight: 0.65mg; Datasheet: Y:\MIS_DATABASE\DATASHEETS\CAPACITORS\885012105013.PDF
C211 = CAP: CAP CERAMIC 10uF 35V 20% X5R 0603; Chkd/date: MANIRAJA/170519; Crtd /date: ALVY/160519; Custom_Duty: 15%; Customs_HS_Code: 85322990; Distributor_name: DIGIKEY; Distributor_part_number: 490-13248-1-ND; Footprint Path: Y:\MIS_DATABASE\Library\ALTIUM_TOOL\PCB_FOOTPRINTS\Altium_Footprint_Lib.PcbLib; Height: 1.00MM; Library Path: Y:\MIS_DATABASE\Library\ALTIUM_TOOL\SCHEMATICS_PARTS\MS_DISCRETE_Library.schlib; Mfr_name: MURATA; Mfr_part_number: GRM188R6YA106MA73D; Mistral Part No: 120019050016-R; Package: 0603; Part_type: CAPACITORS\CERAMIC; Project: BRUKER_SD820_COMMONDO; RoHS: RoHS; Temperature: -55°C+85°C; Tolerance: 20%; Voltage: 35V; Wattage: NA; Weight: 9mg; Datasheet: Y:\MIS_DATABASE\DATASHEETS\CAPACITORS\GRM188R6YA106MA73.PDF
L2 = INDUCTOR: IND HI-CURRENT 1uH 11.5A 20% SMD; Chkd/date: MANIRAJA/280520; Crtd /date: ALVY/280520; Custom_Duty: 24%; Customs_HS_Code: 85437099; Distributor_name: DIGIKEY; Distributor_part_number: 732-6176-1-ND; Footprint Path: Y:\MIS_DATABASE\Library\ALTIUM_TOOL\PCB_FOOTPRINTS\Altium_Footprint_Lib.PcbLib; Height: 4.30MM; Library Path: Y:\MIS_DATABASE\Library\ALTIUM_TOOL\SCHEMATICS_PARTS\MS_DISCRETE_Library.schlib; Mfr_name: WURTH ELECTRONICS; Mfr_part_number: 744316100; Mistral Part No: 130020050041-R; Package: SMD; Project: AM64x-GP_EVM BRD; RoHS: RoHS; Temperature: -40°C+150°C; Tolerance: 20%; Voltage: NA; Wattage: NA; Weight: 570mg; Datasheet: Y:\MIS_DATABASE\DATASHEETS\DISCRETES\INDUCTORS\744316100.PDF
L4 L8 = INDUCTOR: IND POWER 0.47uH 11.5A 20% SMD; Chkd/date: MANIRAJA/130820; Crtd /date: ALVY/130820; Custom_Duty: 24%; Customs_HS_Code: 85437099; Distributor_name: DIGIKEY; Distributor_part_number: 732-3366-1-ND; Footprint Path: Y:\MIS_DATABASE\Library\ALTIUM_TOOL\PCB_FOOTPRINTS\Altium_Footprint_Lib.PcbLib; Height: 3.00MM; Library Path: Y:\MIS_DATABASE\Library\ALTIUM_TOOL\SCHEMATICS_PARTS\MS_DISCRETE_Library.schlib; Mfr_name: WURTH ELECTRONICS; Mfr_part_number: 744373460047; Mistral Part No: 130020080011-R; Package: SMD; Project: AM64x_EVM_BRD; RoHS: RoHS; Temperature: -40°C+125°C; Tolerance: 20%; Voltage: NA; Wattage: NA; Weight: 719mg; Datasheet: Y:\MIS_DATABASE\DATASHEETS\DISCRETES\INDUCTORS\744373460047.PDF
R44 R214 = RESISTOR: RES 10.1K 1/8W 0.1% AUTO 0603; Chkd/date: MANIRAJA/090420; Crtd /date: ALVY/080420; Custom_Duty: 15%; Customs_HS_Code: 85332119; Distributor_name: DIGIKEY; Distributor_part_number: 541-3907-1-ND; Footprint Path: Y:\MIS_DATABASE\Library\ALTIUM_TOOL\PCB_FOOTPRINTS\Altium_Footprint_Lib.PcbLib; Height: 0.55MM; Library Path: Y:\MIS_DATABASE\Library\ALTIUM_TOOL\SCHEMATICS_PARTS\MS_DISCRETE_Library.schlib; Mfr_name: VISHAY; Mfr_part_number: TNPW060310K1BEEA; Mistral Part No: 110020040008-R; Package: 0603; Part_type: RESISTORS\FIXED; Project: AM64x-GP_EVM BRD; RoHS: RoHS; Temperature: -55°C+155°C; Tolerance: 0.1%; Voltage: NA; Wattage: 1/8W; Weight: 25mg; Datasheet: Y:\MIS_DATABASE\DATASHEETS\RESISTORS\VISHAY_TNPWE3.PDF
R49 = RESISTOR: RES 162K 1/10W 1% 0402; Chkd/date: SUHAS/270910; Crtd /date: MUDDU/190610; Custom_Duty: 15%; Customs_HS_Code: 85332119; Distributor_name: DIGIKEY; Distributor_part_number: P162KLCT-ND; Footprint Path: Y:\MIS_DATABASE\Library\ALTIUM_TOOL\PCB_FOOTPRINTS\Altium_Footprint_Lib.PcbLib; Height: 0.40MM; Library Path: Y:\MIS_DATABASE\Library\ALTIUM_TOOL\SCHEMATICS_PARTS\MS_DISCRETE_Library.schlib; Mfr_name: PANASONIC-ECG; Mfr_part_number: ERJ-2RKF1623X; Mistral Part No: 110010060019-R; Package: 0402; Part_type: RESISTORS\FIXED; Project: CENTAURUS; RoHS: RoHS; Temperature: -55°C+155°C; Tolerance: 1%; Voltage: NA; Wattage: 1/10W; Weight: 0.8mg; Datasheet: Y:\MIS_DATABASE\DATASHEETS\RESISTORS\PAN-ERJSER_NOV17.PDF
R58 R117 R123 R219 = RESISTOR: RES 100K 1/16W 5% 0402; Chkd/date: VASANTHA/061216; Crtd /date: BAVISH/010611; Custom_Duty: 15%; Customs_HS_Code: 85332119; Distributor_name: DIGIKEY; Distributor_part_number: 541-100KJCT-ND; Footprint Path: Y:\MIS_DATABASE\Library\ALTIUM_TOOL\PCB_FOOTPRINTS\Altium_Footprint_Lib.PcbLib; Height: 0.40MM; Library Path: Y:\MIS_DATABASE\Library\ALTIUM_TOOL\SCHEMATICS_PARTS\MS_DISCRETE_Library.schlib; Mfr_name: VISHAY; Mfr_part_number: CRCW0402100KJNED; Mistral Part No: 110011060002-R; Package: 0402; Part_type: RESISTORS\FIXED; Project: AM4515_EVM_LCD; RoHS: RoHS; Temperature: -55°C+155°C; Tolerance: 5%; Voltage: NA; Wattage: 1/16W; Weight: 0.65mg; Datasheet: Y:\MIS_DATABASE\DATASHEETS\RESISTORS\CRCW0603.PDF
R118 = RESISTOR: RES 24.9K 1/16W 1% 0402; Chkd/date: MANIRAJA/080520; Crtd /date: ALVY/070520; Custom_Duty: 15%; Customs_HS_Code: 85332119; Distributor_name: DIGIKEY; Distributor_part_number: 541-24.9KLCT-ND; Footprint Path: Y:\MIS_DATABASE\Library\ALTIUM_TOOL\PCB_FOOTPRINTS\Altium_Footprint_Lib.PcbLib; Height: 0.40MM; Library Path: Y:\MIS_DATABASE\Library\ALTIUM_TOOL\SCHEMATICS_PARTS\MS_DISCRETE_Library.schlib; Mfr_name: VISHAY; Mfr_part_number: CRCW040224K9FKED; Mistral Part No: 110009030538-R; Package: 0402; Part_type: RESISTORS\FIXED; Project: AM64x-GP_EVM BRD; RoHS: RoHS; Temperature: -55°C+155°C; Tolerance: 1%; Voltage: NA; Wattage: 1/16W; Weight: 0.65mg; Datasheet: Y:\MIS_DATABASE\DATASHEETS\RESISTORS\CRCW0603.PDF
R144 = RESISTOR: RES 47.5K 1/16W 1% 0402; Chkd/date: MANIRAJA/170320; Crtd /date: MANIRAJA/170320; Custom_Duty: 15%; Customs_HS_Code: 85332119; Distributor_name: DIGIKEY; Distributor_part_number: 541-47.5KLCT-ND; Footprint Path: Y:\MIS_DATABASE\Library\ALTIUM_TOOL\PCB_FOOTPRINTS\Altium_Footprint_Lib.PcbLib; Height: 0.40MM; Library Path: Y:\MIS_DATABASE\Library\ALTIUM_TOOL\SCHEMATICS_PARTS\MS_DISCRETE_Library.schlib; Mfr_name: VISHAY; Mfr_part_number: CRCW040247K5FKED; Mistral Part No: 110017010006-R; Package: 0402; Part_type: RESISTORS\FIXED; Project: TPR12_SVB; RoHS: RoHS; Temperature: -55°C+155°C; Tolerance: 1%; Voltage: NA; Wattage: 1/16W; Weight: 0.65mg; Datasheet: Y:\MIS_DATABASE\DATASHEETS\RESISTORS\CRCW0603.PDF
R145 R213 = RESISTOR: RES 21K 1/16W 1% 0402; Chkd/date: MANIRAJA/200319; Crtd /date: MANIRAJA/200319; Custom_Duty: 15%; Customs_HS_Code: 85332119; Distributor_name: DIGIKEY; Distributor_part_number: 311-21.0KLRCT-ND; Footprint Path: Y:\MIS_DATABASE\Library\ALTIUM_TOOL\PCB_FOOTPRINTS\Altium_Footprint_Lib.PcbLib; Height: 0.40MM; Library Path: Y:\MIS_DATABASE\Library\ALTIUM_TOOL\SCHEMATICS_PARTS\MS_DISCRETE_Library.schlib; Mfr_name: YAGEO AMERICA; Mfr_part_number: RC0402FR-0721KL; Mistral Part No: 110015080019-R; Package: 0402; Part_type: RESISTORS\FIXED; Project: OCTASIC_3000; RoHS: RoHS; Temperature: -55°C+155°C; Tolerance: 1%; Voltage: NA; Wattage: 1/16W; Weight: 0.65mg; Datasheet: Y:\MIS_DATABASE\DATASHEETS\RESISTORS\RCXXXXL-SER_MAR18.PDF
TP4 TP8 TP10 TP14 TP23 TP29 TP51 TP52 = TESTPOINT: TESTPOINT 1.0MM DRILL PTH; Chkd/date: MAZHAR/271211; Crtd /date: SHREESHAIL/041005; Distributor_name: NA; Distributor_part_number: NA; Height: NA; Mfr_name: LOCAL; Mistral Part No: 130009030938; Package: THRU-HOLE; Project: HSE; Datasheet: NA
U5 = TPS62097RWKT_VQFNHR11: IC 2A SYNCHRONOUS STEP DOWN CONVERTER WITH IDCS CONTROL VQFN-HR11; Chkd/date: MANIRAJA/270917; Crtd /date: MANIRAJA/270917; Custom_Duty: 15%; Customs_HS_Code: 85423100; Distributor_name: DIGIKEY; Distributor_part_number: 296-43330-1-ND; Height: 1.00MM; Mfr_name: TEXAS INSTRUMENTS; Mistral Part No: 142017090025-R; Package: VQFN-HR11; Part_type: ICS\POWER\CONVERTER; Project: TI_MAXIE_CPB; RoHS: RoHS; Temperature: -40°C+125°C; Tolerance: NA; Voltage: NA; Wattage: NA; Weight: NA; Datasheet: Y:\MIS_DATABASE\DATASHEETS\ICS\POWER\TPS62097.PDF
U12 = TPS82084_USIP8: IC 2A STEP DOWN CONVERTER MICROSIP POWER MODULE WITH INTEGRATED INDUCTOR uSIP8; Chkd/date: MANIRAJA/090420; Crtd /date: ALVY/080420; Custom_Duty: 15%; Customs_HS_Code: 85423100; Distributor_name: DIGIKEY; Distributor_part_number: 296-42973-1-ND; Footprint Path: Y:\MIS_DATABASE\Library\ALTIUM_TOOL\PCB_FOOTPRINTS\Altium_Footprint_Lib.PcbLib; Height: 1.33MM; Library Path: Y:\MIS_DATABASE\Library\ALTIUM_TOOL\SCHEMATICS_PARTS\MS_MISCPOWER_Library.schlib; Library Ref: TPS82084_uSIP8; Mfr_name: TEXAS INSTRUMENTS; Mistral Part No: 142020040012-R; Package: uSIP8; Part_type: ICS\POWER\POWER MODULE; Project: AM64x-GP_EVM BRD; RoHS: RoHS; Temperature: -40°C+125°C; Tolerance: NA; Voltage: NA; Wattage: NA; Weight: 580mg; Datasheet: Y:\MIS_DATABASE\DATASHEETS\ICS\POWER\TPS8208X.PDF
U25 = TPS62823_VSONHR8: IC 3A ADJ STEP-DOWN CONVERTER WITH 1% ACCURACY VSON-HR8; Chkd/date: MANIRAJA/080520; Crtd /date: ALVY/070520; Custom_Duty: 15%; Customs_HS_Code: 85423100; Distributor_name: DIGIKEY; Distributor_part_number: 296-50225-1-ND; Footprint Path: Y:\MIS_DATABASE\Library\ALTIUM_TOOL\PCB_FOOTPRINTS\Altium_Footprint_Lib.PcbLib; Height: 1.00MM; Library Path: Y:\MIS_DATABASE\Library\ALTIUM_TOOL\SCHEMATICS_PARTS\MS_MISCPOWER_Library.schlib; Mfr_name: TEXAS INSTRUMENTS; Mistral Part No: 142020050005-R; Package: VSON-HR8; Part_type: ICS\POWER\DC-DC CONVERTER; Project: AM64x-GP_EVM BRD; RoHS: RoHS; Temperature: -40°C+125°C; Tolerance: NA; Voltage: NA; Wattage: NA; Weight: 6.2mg; Datasheet: Y:\MIS_DATABASE\DATASHEETS\ICS\POWER\TPS62821-2-3.PDF
U33 = TPS74501_WSON6: IC 1A ADJ OUTPUT LDO WITH POWER-GOOD WSON6; Chkd/date: MANIRAJA/060619; Crtd /date: ALVY/060619; Custom_Duty: 15%; Customs_HS_Code: 85423100; Distributor_name: MOUSER; Distributor_part_number: 595-TPS74601PDRVR; Footprint Path: Y:\MIS_DATABASE\Library\ALTIUM_TOOL\PCB_FOOTPRINTS\Altium_Footprint_Lib.PcbLib; Height: 0.80MM; Library Path: Y:\MIS_DATABASE\Library\ALTIUM_TOOL\SCHEMATICS_PARTS\MS_MISCPOWER_Library.schlib; Mfr_name: TEXAS INSTRUMENTS; Mistral Part No: 142019060004-R; Package: WSON6; Part_type: ICS\POWER\VOLTAGE REGULATOR; Project: TI_MAXIE_CPB; RoHS: RoHS; Temperature: -40°C+125°C; Tolerance: NA; Voltage: NA; Wattage: NA; Weight: NA; Datasheet: Y:\MIS_DATABASE\DATASHEETS\ICS\POWER\TPS74601.PDF
U65 = TPS62085RLTR_VSONHR7: IC 3A 1.8V STEP DOWN CONVERTER WITH SHORT CIRCUIT PROTECTION VSON-HR7; Chkd/date: MANIRAJA/310818; Crtd /date: MANIRAJA/310818; Custom_Duty: 15%; Customs_HS_Code: 85423100; Distributor_name: DIGIKEY; Distributor_part_number: 296-37087-1-ND; Footprint Path: Y:\MIS_DATABASE\Library\ALTIUM_TOOL\PCB_FOOTPRINTS\Altium_Footprint_Lib.PcbLib; Height: 1.00MM; Library Path: Y:\MIS_DATABASE\Library\ALTIUM_TOOL\SCHEMATICS_PARTS\MS_MISCPOWER_Library.schlib; Mfr_name: TEXAS INSTRUMENTS; Mistral Part No: 142018080020-R; Package: VSON-HR7; Part_type: ICS\POWER\CONVERTER; Project: TI_MAXIE_CPB; RoHS: RoHS; Temperature: -40°C+125°C; Tolerance: NA; Voltage: NA; Wattage: NA; Weight: 8.8mg; Datasheet: Y:\MIS_DATABASE\DATASHEETS\ICS\POWER\TPS62085.PDF
U72 = TLV71318PDQNR_X2SON4: IC 500mA LOW IQ LDO REGULATOR X2SON-4; Crtd /date: ALVY/160620; Custom_Duty: 15%; Customs_HS_Code: 85423100; Distributor_name: DIGIKEY; Distributor_part_number: 296-51790-1-ND; Footprint Path: Y:\MIS_DATABASE\Library\ALTIUM_TOOL\PCB_FOOTPRINTS\Altium_Footprint_Lib.PcbLib; Height: 0.40MM; Library Path: Y:\MIS_DATABASE\Library\ALTIUM_TOOL\SCHEMATICS_PARTS\MS_MISCPOWER_Library.schlib; Mfr_name: TEXAS INSTRUMENTS; Mistral Part No: 142020060013-R; Package: X2SON-4; Part_type: ICS\POWER\VOLTAGE REGULATOR; Project: AM64x-GP_EVM BRD; RoHS: RoHS; Temperature: -40°C+125°C; Tolerance: NA; Voltage: NA; Wattage: NA; Weight: 1.1mg; Datasheet: Y:\MIS_DATABASE\DATASHEETS\ICS\POWER\TLV755P.PDF
U103 = SN74LVC1G32DBVR_SOT23-5: IC SINGAL 2 INPUT POSITIVE OR GATE SOT23-5; Chkd/date: MANIRAJA/051017; Crtd /date: MAZHAR/070806; Custom_Duty: 15%; Customs_HS_Code: 85423100; Distributor_name: DIGIKEY; Distributor_part_number: 296-9847-1-ND; Height: 1.45MM; Mfr_name: TEXAS INSTRUMENTS; Mistral Part No: 141009030236-R; Package: SOT23-5; Part_type: ICS\DIGITAL\GATES; Project: SVDO_RMB_MMA; RoHS: RoHS; Temperature: -40°C+85°C; Tolerance: NA; Voltage: NA; Wattage: NA; Weight: 6.3mg; Datasheet: Y:\MIS_DATABASE\DATASHEETS\ICS\DIGITAL\GATES\SN74LVC1G32.PDF
U104 = SN74LVC1G08DBVRE4_SOT23-5: IC SINGLE 2-INPUT POSITIVE AND GATE SOT23-5; Chkd/date: SUHAS/221010; Crtd /date: USMAN/151008; Custom_Duty: 15%; Customs_HS_Code: 85423100; Distributor_name: DIGIKEY; Distributor_part_number: SN74LVC1G08DBVRE4-ND; Height: 1.45MM; Mfr_name: TEXAS INSTRUMENTS; Mistral Part No: 141009060026-R; Part_type: ICS\DIGITAL\GATES; Project: KHAN_MAIN; RoHS: Sb/ Br FREE; Temperature: -40°C+85°C; Datasheet: Y:\MIS_DATABASE\DATASHEETS\ICS\DIGITAL\GATES\SN74LVC1G08.PDF

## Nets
DGND: C9.2 C10.2 C17.2 C20.2 C21.1 C22.1 C30.1 C31.1 C32.2 C33.2 C37.2 C45.2 C50.2 C55.1 C72.1 C77.2 C95.2 C109.2 C117.1 C126.2 C129.2 C202.2 C211.2 C217.2 C221.1 C243.2 C265.2 C403.2 C444.1 C479.2 C486.2 C495.1 J4.3 J5.1 R49.2 R117.1 R145.2 R213.2 R263.1 R452.1 U1.7(GND) U5.1(PGND) U5.11(AGND) U6.1(A1) U6.7(GND) U10.2(GND) U11.7(GND) U12.5(GND) U12.6(GND) U12.9(EP) U14.1(A1) U14.2(A0) U14.7(GND) U16.2(A0) U16.7(GND) U25.3(AGND) U25.5(PGND) U28.7(GND) U33.3(GND) U33.7(EP) U65.5(GND) U72.2(GND) U72.5(EP) U91.25(GND) U91.33(EP) U103.3(GND) U104.3(GND) ; also on sheet 2 3 4 5 6 7 8 9 10 11 12 16 17 18 19 20 21 22 23 24 25 26 27 28 29 30 39 40
VCC1V2_DDR: C20.1 C21.2 J8.1 L2.2 R22.1 R214.1 TP4.1(TP) U5.3(VOS)
VCC1V2_PG: R219.1 U5.5(PG) U103.1(A) U104.1(A) ; also on sheet 8
VCC1V8: C30.2 C217.1 C221.2 J13.1 L8.2 R24.2 R233.2 TP51.1(TP) U10.3(VCCA) U65.3(FB) U65.4(VOS) ; also on sheet 11 12 18 21 24
VCC3V3_PREREG: C9.1 C37.1 C95.1 C126.1 C211.1 C265.1 C479.1 C495.2 R58.2 R123.2 R219.2 U5.7(PVIN) U5.8(AVIN) U12.3(VIN1) U12.4(VIN2) U25.7(VIN) U33.6(IN) U65.7(VIN) U72.4(IN) U103.5(VCC) U104.5(VCC) ; also on sheet 17 25
VCC3V3_SYS_PG: R580.2 R583.2 TP49.1(TP) ; also on sheet 16 17
VCC_3V3_SYS: C10.1 C17.1 C22.2 C32.1 C45.1 C50.1 C55.2 C109.1 C444.2 J19.1 R47.2 R143.2 R265.1 R270.1 R295.4 R465.2 U1.1(A1) U1.6(VS+) U6.2(A0) U6.6(VS+) U10.7(VCCB) U11.6(VS+) U14.6(VS+) U16.6(VS+) U28.6(VS+) U91.27(VCCP) U91.31(VCC) ; also on sheet 2 5 6 7 8 10 11 12 16 17 18 19 20 21 23 24 25 26 27 29 30 39 40
VCC_CORE: C72.2 C77.1 C486.1 J20.1 L4.2 R92.3 TP23.1(TP)
VCC_CORE_EN: R584.2 TP24.1(TP) U103.4(Y)
VCC_CORE_FB: C96.2 R117.2 R118.2 U25.2(FB)
VCC_CORE_PG: R123.1 U25.8(PG) U104.2(B) ; also on sheet 8 17
VDD1V8_PG: C403.1 R143.1 R581.2 TP50.1(TP) U33.5(PG) U65.2(PG) ; also on sheet 8
VDD_0V85: C31.2 C33.1 J11.1 R227.4 TP8.1(TP) U12.8(VOUT)
VDD_0V85_EN: R57.1 U104.4(Y)
VDD_0V85_PG: R58.1 U12.2(PG) U103.2(B) ; also on sheet 8
VDD_CORE: C96.1 J20.2 R92.2 R118.1 TP14.1(TP) ; also on sheet 3 4 25
VDD_DDR4: J8.2 R22.4 ; also on sheet 3 4 16 22
VDDA1V8: C117.2 C129.1 J22.1 R144.1 R351.2 TP29.1(TP) U33.1(OUT)
VDDA_1V8: J22.2 R351.3 ; also on sheet 3 4
VDDAR_CORE: J11.2 R44.1 R227.1 TP10.1(TP) ; also on sheet 4
ADDR_1: R452.2 U91.26(ADDR)
CAN_MUX_SEL: U91.2(P01) ; also on sheet 6
CPSW_FET2_SEL: U91.12(P13) ; also on sheet 2
CPSW_FET_SEL: U91.11(P12) ; also on sheet 2
DDR_VTT_EN: U10.5(A1) ; also on sheet 21
DDR_VTT_EN_3V3: U10.8(B1) ; also on sheet 16
FSI_FET_SEL: U91.8(P07) ; also on sheet 19
GPIO_CPSW1_RST: U91.3(P02) ; also on sheet 2
GPIO_eMMC_RSTn: U91.1(P00) ; also on sheet 24
GPIO_OLED_RESETn: U91.15(P16) ; also on sheet 6
GPIO_PCIe_RST_OUT: U91.6(P05) ; also on sheet 5
GPIO_RGMII1_RST: U91.4(P03) ; also on sheet 40
GPIO_RGMII2_RST: U91.5(P04) ; also on sheet 39
INA_ALERT: J4.4 R1.2 R28.2 R43.2 R47.1 R48.2 R122.2 R244.2
IO_EXP_INTn_SDIO: R465.1 U91.32(~{INT}) ; also on sheet 24
MCAN0_STB_3V3: U91.9(P10) ; also on sheet 6
MCAN1_STB_3V3: U91.10(P11) ; also on sheet 6
MCU_SAFETY_ERRORz_1V8: U10.4(A2) ; also on sheet 12
MCU_SAFETY_ERRORz_3V3: U10.1(B2) ; also on sheet 12
MMC1_SD_EN: U91.7(P06) ; also on sheet 24
PRG1_RGMII2_FET_SEL: U91.13(P14) ; also on sheet 39
RESETSTATz: U91.28(~{RESET}) ; also on sheet 5 12 21 24 29
SOC_DVDD1V8: J13.2 R233.3 ; also on sheet 3 4
SoC_DVDD3V3: J19.2 R295.1 ; also on sheet 3 4
SoC_I2C0_SCL: J5.3 ; also on sheet 6 10 18
SoC_I2C0_SDA: J5.2 ; also on sheet 6 10 18
SoC_I2C1_SCL: R13.1 R265.2 U1.5(SCL) U6.5(SCL) U11.2(A0) U11.5(SCL) U14.5(SCL) U16.1(A1) U16.5(SCL) U28.1(A1) U28.5(SCL) U91.29(SCL) ; also on sheet 5 6 7 10 30
SoC_I2C1_SDA: R12.1 R270.2 U1.2(A0) U1.4(SDA) U6.4(SDA) U11.1(A1) U11.4(SDA) U14.4(SDA) U16.4(SDA) U28.2(A0) U28.4(SDA) U91.30(SDA) ; also on sheet 5 6 7 10 30
TEST_GPIO2: U91.14(P15) ; also on sheet 30
TEST_LED1: U91.17(P20) ; also on sheet 21
VPP_1V8: C243.1 TP52.1(TP) U72.1(OUT) ; also on sheet 4
VPP_LDO_EN: R263.2 R582.2 TP53.1(TP) U91.16(P17)
N15854407: R43.1 U14.3(ALERT)
N15854417: C47.2 R73.1 U14.8(VBUS) U14.9(VIN-)
N15854427: C47.1 R74.1 U14.10(VIN+)
N15854463: R28.1 U6.3(ALERT)
N15854467: C204.2 R216.1 U6.8(VBUS) U6.9(VIN-)
N15854483: C204.1 R215.1 U6.10(VIN+)
N15854545: R244.1 U11.3(ALERT)
N15854547: R122.1 U28.3(ALERT)
N15854553: C214.2 R229.1 U11.8(VBUS) U11.9(VIN-)
N15854557: C393.2 R350.1 U28.8(VBUS) U28.9(VIN-)
N15854581: C393.1 R352.1 U28.10(VIN+)
N15854603: C214.1 R228.1 U11.10(VIN+)
N15854737: R1.1 U1.3(ALERT)
N15854741: C203.2 R11.1 U1.8(VBUS) U1.9(VIN-)
N15854757: C203.1 R10.1 U1.10(VIN+)
N15854857: J4.2 R12.2
N15854859: J4.1 R13.2
N17682848: R74.2 R92.4
N17682861: R73.2 R92.1
N17683733: R215.2 R227.3
N17683748: R216.2 R227.2
N17685678: R228.2 R233.1
N17685693: R229.2 R233.4
N17685736: R351.1 R352.2
N17685749: R350.2 R351.4
N17686321: R10.2 R22.2
N17686333: R11.2 R22.3
N24972917: R280.2 R295.3
N24972919: R281.2 R295.2
N24972921: C269.2 R281.1 U16.8(VBUS) U16.9(VIN-)
N24972925: C269.1 R280.1 U16.10(VIN+)
N24973001: R48.1 U16.3(ALERT)
N26648719: TP92.1(TP) U91.18(P21)
N26648730: TP90.1(TP) U91.19(P22)
N26648748: TP88.1(TP) U91.20(P23)
N26648766: TP87.1(TP) U91.21(P24)
N26648784: TP86.1(TP) U91.22(P25)
N26648802: TP89.1(TP) U91.23(P26)
N26648820: TP91.1(TP) U91.24(P27)
N26735382: C202.1 U5.9(SS/TR)
N26735416: R213.1 R214.2 U5.4(FB)
N26735457: L2.1 U5.2(SW)
N26735496: L8.1 U65.6(SW)
N26735653: R144.2 R145.1 U33.2(FB)
N26736579: L4.1 U25.6(SW)
N26736751: R57.2 U12.1(EN)
N26736805: R44.2 R49.1 U12.7(FB)
N27838027: R24.1 U10.6(OE)
N27943339: R580.1 U65.1(EN)
N27943633: R581.1 U5.6(EN)
N27943804: R582.1 U72.3(EN)
N27943890: R583.1 U33.4(EN)
N27943939: R584.1 U25.1(EN)

Not connected (* = marked no-connect by the designer): J4 5*; U5 10(MODE)*; U25 4(NC)*

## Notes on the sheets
sheet 13
- IO EXPANDER
- I2C ADDRESS: 0x22
- Off Page Connections
- I2C TEST HEADER
- 3V3 IO level
- SCL
- GND
- SDA
- From Safety Connector
- From SoC OSPI Section
- To Processor
- To SoC MMC
- To VTT Reg
- LEVEL TRANSLATOR
sheet 14
- CURRENT MONITORING  DEVICES
- VDD_CORE
- SoC_DVDD1V8
- I2C ADDRESS: 0x40
- I2C ADDRESS: 0x4B
- VDDAR_CORE
- VDDA_1V8
- I2C ADDRESS: 0x41
- I2C ADDRESS: 0x4E
- SoC_DVDD3V3
- VDD_DDR4
- INA I2C SLAVE ADDRESS
- I2C ADDRESS: 0x4C
- SLAVE
  ADDRESS
  (IN HEX)
- I2C ADDRESS: 0x46
- POWER SOURCE
- SUPPLY NET
- VCC_CORE
- VDD_CORE
- 40
- VDD_0V85
- VDDAR_CORE
- 41
- VCC_3V3_SYS
- SoC_DVDD3V3
- 4C
- VCC1V8
- SoC_DVDD1V8
- 4B
- VDDA1V8
- VDDA_1V8
- 4E
- VCC1V2_DDR
- VDD_DDR4
- 46
sheet 15
- SoC POWER SUPPLY
- 1.8V IO, 3.0AMPS SUPPLY
- 0.75 / 0.8 /0.85V, 3.0AMPS SUPPLY
- Rfb
- CORE VOLTAGE
- Rfb RES TO BE PLACED
- 0.75V
- Rfb = 24.9K
- 1.2V, 2.0AMPS SUPPLY
- 0.80V
- Rfb = 33.2K
- 0.85V
- Rfb = 41.2K
- 0.85 V, 1.5AMPS SUPPLY
- Ren
- 1.8V VPP, 0.15AMPS SUPPLY
- If VDD_CORE = 0.75V,
  Mount Ren
  If VDD_CORE =0.85
  DNI Ren
- 1.8V Analog , 1AMPS SUPPLY
- Off Page Connections
